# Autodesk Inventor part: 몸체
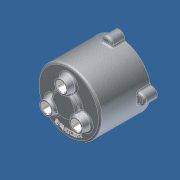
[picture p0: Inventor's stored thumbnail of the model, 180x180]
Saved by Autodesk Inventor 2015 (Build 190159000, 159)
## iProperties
Created: 2012-05
Part Number: 몸체
Document SubType Name: 모델링
Designer: SeoGD™
Material: 일반
Appearance: 기본값
변환 표준: STEP AP214IS
파일 이름: C:\Users\SeoGD\Desktop\?쒗뿕\紐몄껜.stp
전처리기: Build: 253, Release: 2010 SP1 - Date: Wed 07/29/2009
전송 단위: 밀리미터
불확실성: 0.01
Author: SeoGD™
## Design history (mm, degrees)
sketch "스케치2"
  geometry: C1 r 50 at (0, 0); 1 further point
  constraints: 1 centre point, 1 coincident
  dimensions: "d9" = 100 diameter of C1
extrude "돌출2" new body sketch "스케치2" distance "d10" = 80; taper "d11" = 0 deg
feature "쉘1" dims "d12" = 5
sketch "스케치3" dims "d13" = 55
  geometry: C1 r 7.5 at (0, 27.5); C2 r 12.5 at (0, 27.5); 2 further points
  constraints: 2 centre point, 2 coincident, 2 vertical alignment, 2 other
  dimensions: "d14" = 15 diameter of C1; "d15" = 25 diameter of C2
extrude "돌출3" join sketch "스케치3" distance "d16" = 12; taper "d17" = -10 deg
hole "구멍2" diameter "d20" = 15; stored, may be unused: countersink angle "d24" = 90 deg, drill point angle "d26" = 118 deg; dims "d18" = 10, "d19" = 10, "d21" = 6, "d22" = 4, "d23" = 2, "d25" = 15
chamfer "모따기1" distance "d27" = 1; stored, may be unused: second distance "d28" = 2, angle "d29" = 45 deg
sketch "스케치4"
  geometry: L1 (0, 0)-(0, 88); L2 (0, 70)-(13.16, 70); L3 (-45, 75)-(45, 75) reference; L4 (-50, 80)-(50, 80) reference; L5 (13.16, 70)-(14.5, 75); L6 (20, 80)-(20, 88); L7 (20, 88)-(0, 88); L8 (20, 80)-(14.5, 75)
  constraints: 12 end point, 3 point on line, 2 perpendicular, 1 vertical
  dimensions: "d34" = 40 diameter of L6 L1; "d35" = 105 deg angle of L5 L3; "d36" = 5 distance between parallel lines of L2 L3; "d37" = 8 distance between parallel lines of L7 L4; "d51" = 29 diameter of L5.end L1
revolve "회전1" sketch "스케치4" stored, may be unused: angle "d38" = 90 deg
hole "구멍3" diameter "d41" = 15; stored, may be unused: countersink angle "d45" = 90 deg, drill point angle "d47" = 0 deg; dims "d39" = 10, "d40" = 10, "d42" = 6, "d43" = 22, "d44" = 13, "d46" = 15
chamfer "모따기2" distance "d48" = 1; stored, may be unused: second distance "d49" = 2, angle "d50" = 45 deg
fillet "모깎기1" dims "d52" = 3
fillet "모깎기2" dims "d53" = 3, "d72" = 0.2
sketch "스케치5"
  geometry: A1 r 50 centre (0, 0) between (50, 0) and (-8.074, 49.344) reference; A2 r 8.5 centre (0, 52) between (8.074, 49.344) and (-8.074, 49.344); 1 further point
  constraints: 5 point on circle, 1 centre point, 1 horizontal alignment
  dimensions: "d54" = 90 deg dimension on point (0, 0) A2.centre A1.start; "d55" = 52 distance of A2.centre point (0, 0); "d56" = 17 diameter of A2
extrude "돌출4" join sketch "스케치5" distance "d57" = 20; taper "d58" = 0 deg
fillet "모깎기3" dims "d59" = 3
hole "구멍4" diameter "d62" = 4.134; stored, may be unused: countersink angle "d66" = 90 deg, drill point angle "d68" = 118 deg; dims "d60" = 10, "d61" = 10, "d63" = 12, "d64" = 22, "d65" = 13, "d67" = 15
sketch "스케치6"
  geometry: C1 r 47 at (0, 0) reference; C2 r 42.5 at (0, 0); 1 further point
  constraints: 1 centre point, 1 coincident, 1 other
  dimensions: "d73" = 85 diameter of C2
feature "엠보싱1" sketch "스케치6" dims "d74" = 1, "d75" = 0
node "솔리드1"
node "솔리드 본체"
node "곡면 본체"
pattern_circular "원형 패턴1" dims "d31" = 360 deg
pattern_circular "원형 패턴2" dims "d70" = 360 deg
node "솔리드2"
